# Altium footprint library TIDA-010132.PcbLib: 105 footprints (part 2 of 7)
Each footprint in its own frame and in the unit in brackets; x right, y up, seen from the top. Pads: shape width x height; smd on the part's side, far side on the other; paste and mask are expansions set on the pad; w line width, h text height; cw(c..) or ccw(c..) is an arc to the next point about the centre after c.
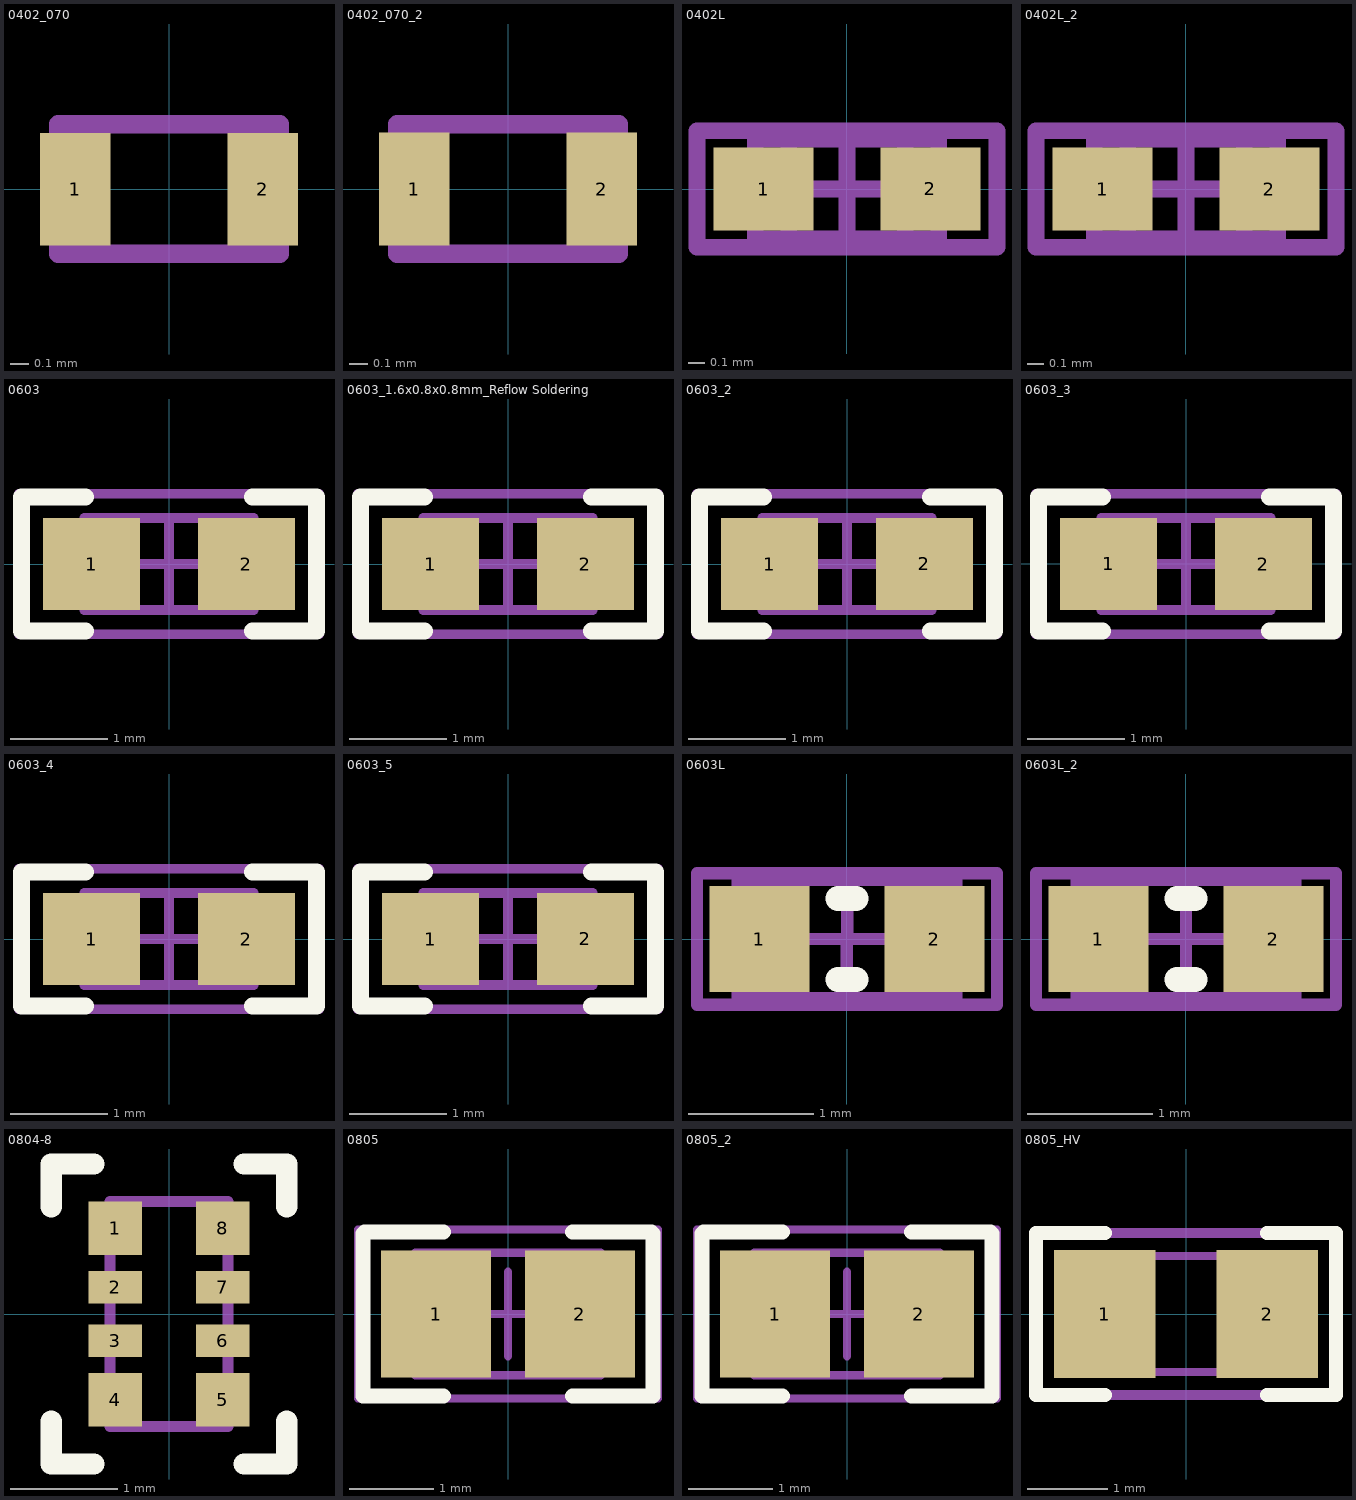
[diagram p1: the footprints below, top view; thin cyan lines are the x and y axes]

## 0402_070 [mil] "SMD, 2-Leads, Body 1.2x0.7mm, Height 0.7mm"
height 27.56
pads (2):
  rect 15x24 smd: 1(-20,0) 2(20,0)
Mechanical 5:
  lines w3.94: -23.62,-13.78 -23.62,13.78 23.62,13.78 23.62,-13.78 -23.62,-13.78
  text ".Designator" at -21.65,-5.91 h18
3D body: height 27.56, standoff 0, extent 13.78,-13.78 23.62,13.78
3D body: height 27.56, standoff 0, extent -23.62,-13.78 -13.78,13.78
3D body: height 27.56, standoff 0, extent -13.78,-13.78 13.78,13.78

## 0402_070_2 [mil]
pads (2):
  rect 15x24 smd: 1(-20,0) 2(20,0)
Mechanical 5:
  lines w3.94: -23.62,-13.78 -23.62,13.78 23.62,13.78 23.62,-13.78 -23.62,-13.78
  text ".Designator" at -21.65,-5.91 h18
3D body: height 27.56, standoff 0, extent 13.78,-13.78 23.62,13.78
3D body: height 27.56, standoff 0, extent -23.62,-13.78 -13.78,13.78
3D body: height 27.56, standoff 0, extent -13.78,-13.78 13.78,13.78

## 0402L [mm] "0402 from SM-752 data"
height 0.6
pads (2):
  rect 0.6x0.5 smd: 1(-0.5,0) 2(0.5,0)
Mechanical 5:
  lines w0.1: -0.9,-0.35 0.9,-0.35 0.9,0.35 -0.9,0.35 -0.9,-0.35
  text ".Designator" at -0.951,0.613 h0.46
Mechanical 13:
  lines w0.1: -0.35,-0.3 -0.35,0.3 ; 0.35,-0.3 0.35,0.3 ; -0.55,-0.3 -0.55,0.3 0.55,0.3 0.55,-0.3 -0.55,-0.3
Mechanical 15:
  lines w0.1: -0.3,0 0.3,0 ; 0,-0.3 0,0.3 ; -0.9,-0.35 -0.9,0.35 0.9,0.35 0.9,-0.35 -0.9,-0.35
3D body: height 0.6, standoff 0, extent -0.549,-0.299 -0.351,0.299
3D body: height 0.6, standoff 0, extent -0.349,-0.299 0.349,0.299
3D body: height 0.6, standoff 0, extent 0.351,-0.299 0.549,0.299

## 0402L_2 [mm]
pads (2):
  rect 0.6x0.5 smd: 1(-0.5,0) 2(0.5,0)
Mechanical 5:
  lines w0.1: -0.9,-0.35 0.9,-0.35 0.9,0.35 -0.9,0.35 -0.9,-0.35
  text ".Designator" at 1.064,1.069 h0.46
Mechanical 13:
  lines w0.1: -0.35,-0.3 -0.35,0.3 ; 0.35,-0.3 0.35,0.3 ; -0.55,-0.3 -0.55,0.3 0.55,0.3 0.55,-0.3 -0.55,-0.3
Mechanical 15:
  lines w0.1: -0.3,0 0.3,0 ; 0,-0.3 0,0.3 ; -0.9,-0.35 -0.9,0.35 0.9,0.35 0.9,-0.35 -0.9,-0.35
3D body: height 0.6, standoff 0, extent -0.549,-0.299 -0.351,0.299
3D body: height 0.6, standoff 0, extent -0.349,-0.299 0.35,0.299
3D body: height 0.6, standoff 0, extent 0.351,-0.299 0.549,0.299

## 0603 [mm] "0603 from SM-752 data"
height 1
pads (2):
  rect 1x0.95 smd: 1(-0.8,0) 2(0.8,0)
Top Overlay:
  lines w0.178: -0.864,-0.691 -1.524,-0.691 -1.524,0.693 -0.864,0.693 ; 0.864,-0.691 1.524,-0.691 1.524,0.693 0.864,0.693
Mechanical 5:
  lines w0.1: -1.55,-0.725 1.55,-0.725 1.55,0.725 -1.55,0.725 -1.55,-0.725
  text ".Designator" at -1.397,-0.381 h0.46
Mechanical 13:
  lines w0.1: -0.55,-0.475 -0.55,0.475 ; 0.55,-0.475 0.55,0.475 ; -0.875,-0.475 -0.875,0.475 0.875,0.475 0.875,-0.475 -0.875,-0.475
Mechanical 15:
  lines w0.1: -0.475,0 0.475,0 ; 0,-0.475 0,0.475 ; -1.55,-0.725 -1.55,0.725 1.55,0.725 1.55,-0.725 -1.55,-0.725
3D body: height 1, standoff 0, extent 0.551,-0.474 0.874,0.474
3D body: height 1, standoff 0, extent -0.549,-0.474 0.549,0.474
3D body: height 1, standoff 0, extent -0.874,-0.474 -0.551,0.474

## 0603_1.6x0.8x0.8mm_Reflow Soldering [mm]
pads (2):
  rect 1x0.95 smd: 1(-0.8,0) 2(0.8,0)
Top Overlay:
  lines w0.178: -0.864,-0.691 -1.524,-0.691 -1.524,0.693 -0.864,0.693 ; 0.864,-0.691 1.524,-0.691 1.524,0.693 0.864,0.693
Mechanical 5:
  lines w0.1: -1.55,-0.725 -1.55,0.725 1.55,0.725 1.55,-0.725 -1.55,-0.725
  text ".Designator" at -1.397,-0.381 h0.46
Mechanical 13:
  lines w0.1: -0.55,-0.475 -0.55,0.475 ; 0.55,-0.475 0.55,0.475 ; -0.875,-0.475 0.875,-0.475 0.875,0.475 -0.875,0.475 -0.875,-0.475
Mechanical 15:
  lines w0.1: -0.475,0 0.475,0 ; 0,-0.475 0,0.475 ; -1.55,-0.725 1.55,-0.725 1.55,0.725 -1.55,0.725 -1.55,-0.725
3D body: height 1, standoff 0, extent -0.874,-0.474 -0.551,0.474
3D body: height 1, standoff 0, extent -0.549,-0.474 0.549,0.474
3D body: height 1, standoff 0, extent 0.551,-0.474 0.874,0.474

## 0603_2 [mm]
pads (2):
  rect 1x0.95 smd: 1(-0.8,0) 2(0.8,0)
Top Overlay:
  lines w0.178: -0.864,-0.691 -1.524,-0.691 -1.524,0.693 -0.864,0.693 ; 0.864,-0.691 1.524,-0.691 1.524,0.693 0.864,0.693
Mechanical 5:
  lines w0.1: -1.55,-0.725 1.55,-0.725 1.55,0.725 -1.55,0.725 -1.55,-0.725
  text ".Designator" at -1.397,-0.381 h0.46
Mechanical 13:
  lines w0.1: -0.55,-0.475 -0.55,0.475 ; 0.55,-0.475 0.55,0.475 ; -0.875,-0.475 -0.875,0.475 0.875,0.475 0.875,-0.475 -0.875,-0.475
Mechanical 15:
  lines w0.1: -0.475,0 0.475,0 ; 0,-0.475 0,0.475 ; -1.55,-0.725 -1.55,0.725 1.55,0.725 1.55,-0.725 -1.55,-0.725
3D body: height 1, standoff 0, extent 0.551,-0.474 0.874,0.474
3D body: height 1, standoff 0, extent -0.549,-0.474 0.549,0.474
3D body: height 1, standoff 0, extent -0.874,-0.474 -0.551,0.474

## 0603_3 [mm]
pads (2):
  rect 1x0.95 smd: 1(-0.8,0) 2(0.8,0)
Top Overlay:
  lines w0.178: -0.864,-0.691 -1.524,-0.691 -1.524,0.693 -0.864,0.693 ; 0.864,-0.691 1.524,-0.691 1.524,0.693 0.864,0.693
Mechanical 5:
  lines w0.1: -1.55,-0.725 -1.55,0.725 1.55,0.725 1.55,-0.725 -1.55,-0.725
  text ".Designator" at -1.134,-0.119 h0.46
Mechanical 13:
  lines w0.1: -0.55,-0.475 -0.55,0.475 ; 0.55,-0.475 0.55,0.475 ; -0.875,-0.475 0.875,-0.475 0.875,0.475 -0.875,0.475 -0.875,-0.475
Mechanical 15:
  lines w0.1: -0.475,0 0.475,0 ; 0,-0.475 0,0.475 ; -1.55,-0.725 1.55,-0.725 1.55,0.725 -1.55,0.725 -1.55,-0.725
3D body: height 1, standoff 0, extent -0.874,-0.474 -0.551,0.474
3D body: height 1, standoff 0, extent -0.549,-0.474 0.549,0.474
3D body: height 1, standoff 0, extent 0.551,-0.474 0.874,0.474

## 0603_4 [mm]
pads (2):
  rect 1x0.95 smd: 1(-0.8,0) 2(0.8,0)
Top Overlay:
  lines w0.178: -0.864,-0.691 -1.524,-0.691 -1.524,0.693 -0.864,0.693 ; 0.864,-0.691 1.524,-0.691 1.524,0.693 0.864,0.693
Mechanical 5:
  lines w0.1: -1.55,-0.725 1.55,-0.725 1.55,0.725 -1.55,0.725 -1.55,-0.725
  text ".Designator" at -1.397,-0.381 h0.46
Mechanical 13:
  lines w0.1: -0.55,-0.475 -0.55,0.475 ; 0.55,-0.475 0.55,0.475 ; -0.875,-0.475 -0.875,0.475 0.875,0.475 0.875,-0.475 -0.875,-0.475
Mechanical 15:
  lines w0.1: -0.475,0 0.475,0 ; 0,-0.475 0,0.475 ; -1.55,-0.725 -1.55,0.725 1.55,0.725 1.55,-0.725 -1.55,-0.725
3D body: height 1, standoff 0, extent 0.551,-0.474 0.874,0.474
3D body: height 1, standoff 0, extent -0.549,-0.474 0.549,0.474
3D body: height 1, standoff 0, extent -0.874,-0.474 -0.551,0.474

## 0603_5 [mm]
pads (2):
  rect 1x0.95 smd: 1(-0.8,0) 2(0.8,0)
Top Overlay:
  lines w0.178: -0.864,-0.691 -1.524,-0.691 -1.524,0.693 -0.864,0.693 ; 0.864,-0.691 1.524,-0.691 1.524,0.693 0.864,0.693
Mechanical 5:
  lines w0.1: -1.55,-0.725 1.55,-0.725 1.55,0.725 -1.55,0.725 -1.55,-0.725
  text ".Designator" at -1.397,-0.381 h0.46
Mechanical 13:
  lines w0.1: -0.55,-0.475 -0.55,0.475 ; 0.55,-0.475 0.55,0.475 ; -0.875,-0.475 -0.875,0.475 0.875,0.475 0.875,-0.475 -0.875,-0.475
Mechanical 15:
  lines w0.1: -0.475,0 0.475,0 ; 0,-0.475 0,0.475 ; -1.55,-0.725 -1.55,0.725 1.55,0.725 1.55,-0.725 -1.55,-0.725
3D body: height 1, standoff 0, extent 0.551,-0.474 0.874,0.474
3D body: height 1, standoff 0, extent -0.549,-0.474 0.549,0.474
3D body: height 1, standoff 0, extent -0.874,-0.474 -0.551,0.474

## 0603L [mm] "0603 from SM-752 data"
height 1
pads (2):
  rect 0.8x0.85 smd: 1(-0.7,0) 2(0.7,0)
Top Overlay:
  lines w0.2: -0.071,-0.325 0.071,-0.325 ; -0.071,0.325 0.071,0.325
Mechanical 5:
  lines w0.1: -1.2,-0.525 -1.2,0.525 1.2,0.525 1.2,-0.525 -1.2,-0.525
  text ".Designator" at -1.001,-0.277 h0.46
Mechanical 13:
  lines w0.1: -0.55,-0.475 -0.55,0.475 ; 0.55,-0.475 0.55,0.475 ; -0.875,-0.475 -0.875,0.475 0.875,0.475 0.875,-0.475 -0.875,-0.475
Mechanical 15:
  lines w0.1: -0.475,0 0.475,0 ; 0,-0.475 0,0.475 ; -1.2,-0.525 1.2,-0.525 1.2,0.525 -1.2,0.525 -1.2,-0.525
3D body: height 1, standoff 0, extent 0.551,-0.474 0.874,0.474
3D body: height 1, standoff 0, extent -0.549,-0.474 0.549,0.474
3D body: height 1, standoff 0, extent -0.874,-0.474 -0.551,0.474

## 0603L_2 [mm]
pads (2):
  rect 0.8x0.85 smd: 1(-0.7,0) 2(0.7,0)
Top Overlay:
  lines w0.2: -0.071,-0.325 0.071,-0.325 ; -0.071,0.325 0.071,0.325
Mechanical 5:
  lines w0.1: -1.2,-0.525 -1.2,0.525 1.2,0.525 1.2,-0.525 -1.2,-0.525
  text ".Designator" at 0.816,0.208 h0.46
Mechanical 13:
  lines w0.1: -0.55,-0.475 -0.55,0.475 ; 0.55,-0.475 0.55,0.475 ; -0.875,-0.475 -0.875,0.475 0.875,0.475 0.875,-0.475 -0.875,-0.475
Mechanical 15:
  lines w0.1: -0.475,0 0.475,0 ; 0,-0.475 0,0.475 ; -1.2,-0.525 1.2,-0.525 1.2,0.525 -1.2,0.525 -1.2,-0.525
3D body: height 1, standoff 0, extent 0.551,-0.474 0.874,0.474
3D body: height 1, standoff 0, extent -0.549,-0.474 0.549,0.474
3D body: height 1, standoff 0, extent -0.874,-0.474 -0.551,0.474

## 0804-8 [mm] "SMD, 8-Leads, Body 2x1mm"
height 0.45
pads (8):
  rect 0.5x0.5 smd: 1(-0.5,0.8) 4(-0.5,-0.8) 5(0.5,-0.8) 8(0.5,0.8)
  rect 0.5x0.3 smd: 2(-0.5,0.25) 3(-0.5,-0.25) 6(0.5,-0.25) 7(0.5,0.25)
Top Overlay:
  lines w0.2: -1.1,-1 -1.1,-1.4 -0.7,-1.4 ; -1.1,1 -1.1,1.4 -0.7,1.4 ; 0.7,-1.4 1.1,-1.4 1.1,-1 ; 0.7,1.4 1.1,1.4 1.1,1
Mechanical 5:
  lines w0.1: -0.55,-1.05 -0.55,1.05 0.55,1.05 0.55,-1.05 -0.55,-1.05
  text ".Designator" at -0.3,0.93 h0.46
3D body: height 0.45, standoff 0, extent -0.55,-1.05 0.55,1.05

## 0805 [mm] "0805 from SM-752 data"
height 1.45
pads (2):
  rect 1.3x1.5 smd: 1(-0.85,0) 2(0.85,0)
Top Overlay:
  lines w0.178: -0.762,-0.968 -1.717,-0.968 -1.717,0.95 -1.699,0.968 -0.762,0.968 ; 0.762,-0.968 1.717,-0.968 1.717,0.95 1.699,0.968 0.762,0.968
Mechanical 5:
  lines w0.1: -1.775,-1 -1.775,1 1.775,1 1.775,-1 -1.775,-1
  text ".Designator" at -0.952,-0.34 h0.46
Mechanical 13:
  lines w0.1: -0.65,-0.725 -0.65,0.725 ; 0.65,-0.725 0.65,0.725 ; -1.1,-0.725 -1.1,0.725 1.1,0.725 1.1,-0.725 -1.1,-0.725
Mechanical 15:
  lines w0.1: -0.5,0 0.5,0 ; 0,-0.5 0,0.5 ; -1.775,-1 -1.775,1 1.775,1 1.775,-1 -1.775,-1
3D body: height 1.45, standoff 0, extent 0.651,-0.724 1.099,0.724
3D body: height 1.45, standoff 0, extent -0.649,-0.724 0.649,0.724
3D body: height 1.45, standoff 0, extent -1.099,-0.724 -0.651,0.724

## 0805_2 [mm]
pads (2):
  rect 1.3x1.5 smd: 1(-0.85,0) 2(0.85,0)
Top Overlay:
  lines w0.178: -0.762,-0.968 -1.717,-0.968 -1.717,0.95 -1.699,0.968 -0.762,0.968 ; 0.762,-0.968 1.717,-0.968 1.717,0.95 1.699,0.968 0.762,0.968
Mechanical 5:
  lines w0.1: -1.775,-1 1.775,-1 1.775,1 -1.775,1 -1.775,-1
  text ".Designator" at -1.525,-0.425 h0.46
Mechanical 13:
  lines w0.1: -0.65,-0.725 -0.65,0.725 ; 0.65,-0.725 0.65,0.725 ; -1.1,-0.725 1.1,-0.725 1.1,0.725 -1.1,0.725 -1.1,-0.725
Mechanical 15:
  lines w0.1: -0.5,0 0.5,0 ; 0,-0.5 0,0.5 ; -1.775,-1 1.775,-1 1.775,1 -1.775,1 -1.775,-1
3D body: height 1.45, standoff 0, extent -1.099,-0.724 -0.651,0.724
3D body: height 1.45, standoff 0, extent -0.649,-0.724 0.649,0.724
3D body: height 1.45, standoff 0, extent 0.651,-0.724 1.099,0.724

## 0805_HV [mil] "0805 with 30mil clearance between pads"
height 57.09
pads (2):
  rect 50x63 smd: 1(-40,0) 2(40,0)
Top Overlay:
  lines w7: -40,-40 -74,-40 -74,0 -74,40 -40,40 ; 40,-40 74,-40 74,0 74,40 40,40
Mechanical 5:
  lines w5: -74,-40 74,-40 74,40 -74,40 -74,-40
  text ".Designator" at -64,-17 h18
Mechanical 13:
  lines w3.94: -25.59,-28.54 -25.59,28.54 ; 25.59,-28.54 25.59,28.54 ; -43.31,-28.54 43.31,-28.54 43.31,28.54 -43.31,28.54 -43.31,-28.54
3D body: height 57.09, standoff 0, extent -43.29,-28.52 -25.61,28.52
3D body: height 57.09, standoff 0, extent -25.57,-28.52 25.57,28.52
3D body: height 57.09, standoff 0, extent 25.61,-28.52 43.29,28.52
